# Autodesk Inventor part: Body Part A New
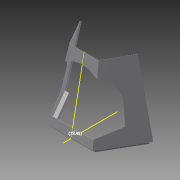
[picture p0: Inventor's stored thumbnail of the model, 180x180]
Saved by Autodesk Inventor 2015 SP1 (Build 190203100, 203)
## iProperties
Created: 2013-06
Part Number: Body Part A New
Material: Steel, Mild
Document SubType Name: Sheet Metal
Designer: 1103005
Density: 1 g/cm^3
Sheet Metal Rule: Default_mm
Flat Pattern Width: 78.9104 cm
Flat Pattern Length: 65.539 cm
Flat Pattern Area: 5171.71 cm^2
Sheet Metal Width: 789.104 mm
Sheet Metal Length: 655.390 mm
Sheet Metal Area: 517171.389 mm^2
Appearance: Steel
Author: 1103005
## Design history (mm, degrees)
sketch "Sketch1"
  geometry: L1 (277.128, 0)-(138.564, -240); L2 (138.564, -240)-(-138.564, -240); L3 (-138.564, -240)-(-277.128, 0); 3 further points
  constraints: 6 end point, 2 horizontal alignment, 1 coincident, 1 midpoint, 1 vertical alignment, 6 other
  dimensions: "d0" = 240 distance from line of point (0, 0) L2
workplane "Work Plane1"
node "Lofted Flange1"
  sketch "Sketch2"
    geometry: L1 (-138.564, -240)-(-277.128, 0) reference; L2 (138.564, -240)-(-138.564, -240) reference; L3 (277.128, 0)-(138.564, -240) reference; L4 (-90.644, -157)-(-181.288, 0); L5 (181.288, 0)-(90.644, -157); L6 (90.644, -157)-(-90.644, -157); 3 further points
    constraints: 6 end point, 2 horizontal alignment, 1 coincident, 1 midpoint, 1 vertical alignment, 6 other
    dimensions: "d2" = 157 distance from line of point (0, 0) L6
sketch "Sketch13"
  geometry: L1 (0.589, -0.23)-(0, 0) reference; L2 (-155.822, 424.77)-(-238.822, -0.23) reference; L3 (-155.822, 424.77)-(-238.822, -0.23) reference; L4 (-286.704, 0)-(48.471, 0) reference
  dimensions: "Flange_Angle_1" = 78.9496 deg angle of L2 L4 (derived)
  node "Projected Loop1"
node "Flange6"
sketch "Sketch16"
  geometry: L1 (22.086, -274.868)-(22.086, 0) reference; L2 (22.086, 0)-(0, 0) reference; L3 (0, 0)-(0, -262.117) reference; L4 (22.086, -274.868)-(0, -262.117) reference; L5 (-59.178, -47.92)-(23.264, -0.322) reference; L6 (-371.411, -228.188)-(-453.853, -275.786) reference; L7 (-215.5, -386.536)-(-442.5, -255.477) reference; L8 (-442.5, -255.477)-(-454.264, -275.853); L9 (-430.589, -262.354)-(-454.264, -275.853); L10 (0, -13.754)-(23.528, 0); L11 (0, 0)-(23.528, 0); 1 further point
  constraints: 8 end point, 4 point on line, 1 horizontal, 1 other
extrude "Extrusion1" cut sketch "Sketch16" stored distance "d106" = 10; taper "d107" = 0 deg
node "Unfold1"
node "Flange10"
sketch "Sketch22"
  geometry: L1 (5.843, 432.74)-(5.843, 432.28) reference; L2 (0, 432.74)-(5.843, 432.74) reference; L3 (0, 0)-(0, 432.74) reference; L4 (5.843, 432.28)-(0, 430.987); L5 (0, 0)-(0, 432.74) reference; L6 (-126.727, 402.479)-(7.922, 432.28) reference; 1 further point
  constraints: 2 end point, 1 parallel, 1 point on line
cut "Cut3" sketch "Sketch22" dims "d144" = 1.2 (= Thickness), "d145" = 0
mirror "Mirror3"
mirror "Mirror4"
node "Refold1"
node "Flange8"
sketch "Sketch23"
  geometry: L1 (83.554, 224.895)-(1.2, 272.442) reference; L2 (-2.356, 274.546)-(-2.356, 270.364) reference; L3 (-2.356, 281.704)-(83.554, 224.895); L4 (-2.356, 270.364)-(-3.861, 270.364); L5 (-3.861, 270.364)-(-2.356, 281.704); 3 further points; 1 other entity
  constraints: 6 end point, 1 horizontal, 1 other
extrude "Extrusion4" cut sketch "Sketch23" stored distance "d146" = 0; taper "d147" = 0 deg
mirror "Mirror5"
sketch "Sketch24"
  geometry: 3 further points; 1 other entity
  constraints: 1 coincident, 3 other
hole "Hole2" sketch "Sketch24" at (13.533, 89.284) diameter "d148" = 7.5; stored, may be unused: countersink angle "d152" = 90 deg, drill point angle "d154" = 118 deg; dims "d149" = 6, "d150" = 4, "d151" = 2, "d153" = 1.2 (= Thickness)
pattern_circular "Circular Pattern2" dims angle "d156" = 120 deg
sketch "Sketch26"
  geometry: L1 (0, 52.86)-(130, 52.86); L2 (130, 52.86)-(199.282, 92.86); L3 (133.146, 45.104)-(132.636, 44.841) reference; L4 (136.882, 2.86)-(-136.882, 2.86) reference; L5 (0, 2.86)-(136.882, 2.86); L6 (132.113, 44.919)-(-132.113, 44.919) reference; L7 (0, 44.919)-(0, 425); L8 (-89.284, 425)-(89.284, 425) reference; L9 (199.282, 92.86)-(177.105, 215.014); L10 (-199.282, 92.86)-(-177.105, 215.014); L11 (-130, 52.86)-(-199.282, 92.86); L12 (0, 52.86)-(-130, 52.86); A1 r 180 centre (0, 182.86) between (177.105, 215.014) and (0, 362.86); A2 r 180 centre (0, 182.86) between (115.638, 44.919) and (124.499, 52.86); A3 r 180 centre (0, 182.86) between (0, 362.86) and (-177.105, 215.014); 1 further point
  constraints: 16 end point, 6 point on circle, 5 point on line, 3 centre point, 3 midpoint, 3 symmetric about line, 2 horizontal, 1 tangent, 1 other
  dimensions: "d159" = 50 distance between parallel lines of L1 L4; "d160" = 150 deg angle of L2 L1; "d162" = 130 distance of L1.start L1.end; "d163" = 80 distance of L1.end L2.end; "d166" = 130 distance from line of L1 A1.centre; "d167" = 180 radius of A1
cut "Cut4" sketch "Sketch26" dims "d168" = 1.2 (= Thickness), "d169" = 0
body "Solid1"
bend "Bend1" dims "d4" = 1.2 (= BendRadius), "d5" = 1.2 (= BendReliefWidth), "d6" = 0.6 (= BendReliefDepth), "d7" = 2.4 (= MinimumRemnant), "d8" = 1.2 (= BendRadius), "SeamGap" = 0.01, "Thickness" = 1.2
sketch "Sketch14"
  geometry: L1 through (-68.942, 119.411) direction (0.5, -0.866); L2 through (10.825, 6.25) direction (0.866, 0.5); L3 (21.651, 12.5)-(-116.233, 251.322); L4 (-116.233, 251.322)-(-137.884, 238.822)
  constraints: 6 end point, 1 perpendicular, 2 other
face "Plate6" dims "d86" = 1.2 (= BendReliefWidth), "d87" = 0.6 (= BendReliefDepth), "d88" = 2.4 (= MinimumRemnant), "d89" = 1.2 (= BendRadius), "d90" = 25, "d91" = 17.63663 (computed from Flange_Angle_1), "d92" = 1.2 (= BendRadius), "d93" = 4.8 (= CornerReliefSize), "d94" = 1, "d95" = 1.2 (= JacobiRadiusSize), "SeamGap" = 0.01, "Thickness" = 1.2
bend "Bend7" dims "d86" = 1.2 (= BendReliefWidth), "d87" = 0.6 (= BendReliefDepth), "d88" = 2.4 (= MinimumRemnant), "d89" = 1.2 (= BendRadius), "d90" = 25, "d91" = 17.63663 (computed from Flange_Angle_1), "d92" = 1.2 (= BendRadius), "SeamGap" = 0.01, "Thickness" = 1.2
feature "Corner6" dims "d90" = 25, "d91" = 17.63663 (computed from Flange_Angle_1), "d93" = 4.8 (= CornerReliefSize), "d94" = 1, "d95" = 1.2 (= JacobiRadiusSize)
node "Projected Loop2"
sketch "Sketch19"
  geometry: L1 through (124.182, 0) direction (-1, -1.43e-16); L2 through (0, -12.5) direction (3.65e-16, -1); L3 (0, -25)-(248.363, -25); L4 (248.363, -25)-(248.363, 0)
  constraints: 6 end point, 1 horizontal, 1 perpendicular, 1 vertical
face "Plate8" dims "d112" = 1.2 (= BendReliefWidth), "d113" = 0.6 (= BendReliefDepth), "d114" = 2.4 (= MinimumRemnant), "d115" = 1.2 (= BendRadius), "d116" = 25, "d117" = 90 deg, "d118" = 1.2 (= BendRadius), "d119" = 4.8 (= CornerReliefSize), "d120" = 1, "d121" = 1.2 (= JacobiRadiusSize), "SeamGap" = 0.01, "Thickness" = 1.2
bend "Bend9" dims "d112" = 1.2 (= BendReliefWidth), "d113" = 0.6 (= BendReliefDepth), "d114" = 2.4 (= MinimumRemnant), "d115" = 1.2 (= BendRadius), "d116" = 25, "d117" = 90 deg, "d118" = 1.2 (= BendRadius), "SeamGap" = 0.01, "Thickness" = 1.2
feature "Corner8" dims "d116" = 25, "d117" = 90 deg, "d119" = 4.8 (= CornerReliefSize), "d120" = 1, "d121" = 1.2 (= JacobiRadiusSize)
sketch "Sketch21"
  geometry: L1 through (47.595, 211.071) direction (-0.22, -0.976); L2 through (4.878, -1.1) direction (0.976, -0.22); L3 (9.755, -2.2)-(104.945, 419.941); L4 (104.945, 419.941)-(95.19, 422.141)
  constraints: 6 end point, 1 perpendicular, 2 other
face "Plate10" dims "d134" = 1.2 (= BendReliefWidth), "d135" = 0.6 (= BendReliefDepth), "d136" = 2.4 (= MinimumRemnant), "d137" = 1.2 (= BendRadius), "d138" = 10, "d139" = 120 deg, "d140" = 1.2 (= BendRadius), "d141" = 4.8 (= CornerReliefSize), "d142" = 1.2 (= GapSize), "d143" = 1.2 (= JacobiRadiusSize), "SeamGap" = 0.01, "Thickness" = 1.2
bend "Bend11" dims "d134" = 1.2 (= BendReliefWidth), "d135" = 0.6 (= BendReliefDepth), "d136" = 2.4 (= MinimumRemnant), "d137" = 1.2 (= BendRadius), "d138" = 10, "d139" = 120 deg, "d140" = 1.2 (= BendRadius), "SeamGap" = 0.01, "Thickness" = 1.2
feature "Corner10" dims "d138" = 10, "d139" = 120 deg, "d141" = 4.8 (= CornerReliefSize), "d142" = 1.2 (= GapSize), "d143" = 1.2 (= JacobiRadiusSize)
feature "Definition1"
other parameters: "BendRadius" = 1.2 (= Thickness), "BendReliefWidth" = 1.2 (= Thickness), "BendReliefDepth" = 0.6 (= 0.5 x Thickness), "CornerReliefSize" = 4.8 (= 4 x Thickness), "MinimumRemnant" = 2.4 (= 2 x Thickness), "TransitionRadius" = 1.2 (= BendRadius), "JacobiRadiusSize" = 1.2 (= BendRadius), "GapSize" = 1.2 (= Thickness), "d1" = 425, "d3" = 0.5, "BendRadius" = 1.2, "BendReliefDepth" = 0.6, "BendReliefWidth" = 1.2, "CornerReliefSize" = 4.8, "GapSize" = 1.2, "JacobiRadiusSize" = 1.2, "MinimumRemnant" = 2.4, "Thickness" = 1.2, "TransitionRadius" = 1.2, "Flange_Angle_1" = 13.7793
